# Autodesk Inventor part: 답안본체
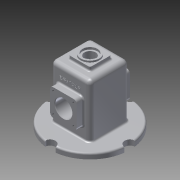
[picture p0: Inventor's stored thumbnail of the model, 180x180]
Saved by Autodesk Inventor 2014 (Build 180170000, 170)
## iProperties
Created: 2018-07
Part Number: 답안본체
Material: Generic
Document SubType Name: Modeling
Designer: kh
Density: 1 g/cm^3
Appearance: Aluminum - Flat
Mass: 336.733 g
Surface Area: 1018.09 cm^2
Volume: 336.733 cm^3
Author: kh
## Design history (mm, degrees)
sketch "Sketch1"
  geometry: C1 r 75 at (0, 0); 1 further point
  constraints: 1 centre point, 1 coincident
  dimensions: "d0" = 150 diameter of C1
extrude "Extrusion1" new body sketch "Sketch1" distance "d1" = 10; taper "d2" = 0 deg
sketch "Sketch2"
  geometry: L1 (0, 0)-(-75, 0); L2 (0, 0)-(0, 75); L3 (0, 0)-(75, 0); L4 (0, 0)-(0, -75); C1 r 10 at (-75, 0); C2 r 10 at (0, 75); C3 r 10 at (75, 0); C4 r 10 at (0, -75); A1 r 75 centre (0, 0) between (-75, 0) and (0, 75) reference; 1 further point
  constraints: 8 end point, 4 centre point, 4 coincident, 4 point on circle, 3 perpendicular, 1 horizontal
  dimensions: "d4" = 20 diameter of C1; "d5" = 20 diameter of C2; "d6" = 20 diameter of C3; "d7" = 20 diameter of C4
extrude "Extrusion2" cut sketch "Sketch2" distance "d8" = 10; taper "d9" = 0 deg
sketch "Sketch3"
  geometry: L1 (37, 37)-(-37, 37); L2 (-37, 37)-(-37, -37); L3 (-37, -37)-(37, -37); L4 (37, -37)-(37, 37); L5 (37, 37)-(-37, -37); L6 (-37, 37)-(37, -37); 1 further point
  constraints: 12 end point, 2 midpoint, 2 parallel, 1 horizontal, 1 perpendicular
  dimensions: "d10" = 74 distance of L1.start L1.end; "d11" = 74 distance of L1.end L2.end
extrude "Extrusion3" join sketch "Sketch3" distance "d12" = 100; taper "d13" = 0 deg
sketch "Sketch4"
  geometry: L1 (62, 70)-(12, 70); L2 (12, 70)-(12, 20); L3 (12, 20)-(62, 20); L4 (62, 20)-(62, 70); L5 (62, 70)-(12, 20); L6 (12, 70)-(62, 20); L7 (46.978, -10)-(27.022, -10) reference; 4 further points
  constraints: 12 end point, 4 midpoint, 2 parallel, 1 horizontal, 1 perpendicular, 1 vertical alignment
  dimensions: "d14" = 50 distance of L1.start L1.end; "d15" = 50 distance of L1.end L2.end; "d16" = 55 distance from line of L7 point (37, 45)
extrude "Extrusion4" join sketch "Sketch4" distance "d17" = 13; taper "d18" = 0 deg
mirror "Mirror1"
sketch "Sketch5"
  geometry: L1 (20, 20)-(-20, 20); L2 (-20, 20)-(-20, -20); L3 (-20, -20)-(20, -20); L4 (20, -20)-(20, 20); L5 (20, 20)-(-20, -20); L6 (-20, 20)-(20, -20); 1 further point
  constraints: 12 end point, 2 midpoint, 2 parallel, 1 horizontal, 1 perpendicular
  dimensions: "d19" = 40 distance of L3.end L2.end; "d20" = 40 distance of L1.end L2.end
extrude "Extrusion5" join sketch "Sketch5" distance "d21" = 7; taper "d22" = 0 deg
sketch "Sketch6"
  geometry: L1 (32, 32)-(-32, 32); L2 (-32, 32)-(-32, -32); L3 (-32, -32)-(32, -32); L4 (32, -32)-(32, 32); L5 (32, 32)-(-32, -32); L6 (-32, 32)-(32, -32); 1 further point
  constraints: 12 end point, 2 midpoint, 2 parallel, 1 horizontal, 1 perpendicular
  dimensions: "d23" = 64 distance of L1.start L1.end; "d24" = 64 distance of L1.end L2.end
extrude "Extrusion6" cut sketch "Sketch6" distance "d25" = 105; taper "d26" = 0 deg
sketch "Sketch7"
  geometry: L1 (-32, 0)-(-32, 105) reference; L2 (-32, 80)-(-25, 77.452); L3 (-32, 55)-(28.433, 55); L4 (32, 0)-(-32, 0) reference; L5 (-25, 77.452)-(-25, 55); 1 further point
  constraints: 6 end point, 3 point on line, 1 perpendicular
  dimensions: "d27" = 55 distance between parallel lines of L4 L3; "d28" = 110 deg angle of L2 L1; "d29" = 7 distance from line of L1 L5.end; "d30" = 50 diameter of L2.start L3
revolve "Revolution1" sketch "Sketch7" stored, may be unused: angle "d31" = 90 deg
mirror "Mirror2"
sketch "Sketch8"
  geometry: C1 r 17.5 at (0, 0); 1 further point
  constraints: 1 centre point, 1 coincident
  dimensions: "d32" = 35 diameter of C1
extrude "Extrusion7" join sketch "Sketch8" distance "d33" = 3; taper "d34" = 0 deg
sketch "Sketch9"
  geometry: C1 r 14 at (0, 0); 1 further point
  constraints: 1 centre point, 1 coincident
  dimensions: "d35" = 28 diameter of C1
extrude "Extrusion8" cut sketch "Sketch9" distance "d36" = 4; taper "d37" = 0 deg
sketch "Sketch10"
  geometry: C1 r 10.5 at (0, 0); 1 further point
  constraints: 1 centre point, 1 coincident
  dimensions: "d38" = 21 diameter of C1
extrude "Extrusion9" cut sketch "Sketch10" stored distance "d39" = 4; taper "d40" = 0 deg
sketch "Sketch11"
  geometry: L1 (62, 70)-(12, 70) reference; L2 (12, 70)-(12, 20) reference; L3 (12, 20)-(62, 20) reference; L4 (62, 20)-(62, 70) reference; L5 (12, 20)-(62, 70); L6 (62, 20)-(12, 70); C1 r 16 at (37, 45); 1 further point
  constraints: 4 end point, 1 centre point, 1 midpoint, 1 perpendicular, 1 point on line
  dimensions: "d41" = 32 diameter of C1
extrude "Extrusion10" cut sketch "Sketch11" stored distance "d42" = 4; taper "d43" = 0 deg
fillet "Fillet1" dims "d44" = 6
sketch "Sketch12"
  geometry: L1 (18, 20)-(56, 20) reference; L2 (62, 26)-(62, 64) reference; L3 (56, 70)-(18, 70) reference; L4 (12, 64)-(12, 26) reference; C1 r 16 at (37, 45) reference; A1 r 6 centre (18, 26) between (12, 26) and (18, 20) reference; A2 r 6 centre (56, 26) between (56, 20) and (62, 26) reference; A3 r 6 centre (56, 64) between (62, 64) and (56, 70) reference; A4 r 6 centre (18, 64) between (18, 70) and (12, 64) reference; 1 further point
  node "Projected Loop3"
hole "Hole1" sketch "Sketch12" diameter "d45" = 3.459; stored, may be unused: countersink angle "d49" = 90 deg, drill point angle "d51" = 118 deg; dims "d46" = 8, "d47" = 4, "d48" = 2, "d50" = 10
mirror "Mirror3"
sketch "Sketch14"
  geometry: L1 (0, 0)-(0, -100) reference; L2 (19.5, -110)-(54.5, -110) reference; 2 further points
  constraints: 1 other
  dimensions: "d52" = 37 distance from line of point (37, -80) L1; "d53" = 30 distance from line of point (37, -80) L2
emboss "Emboss1" sketch "Sketch14" dims "d10" = 74, "d11" = 74, "d54" = 0.5, "d55" = 0
fillet "Fillet2" dims "d56" = 8
chamfer "Chamfer1" distance "d57" = 1; stored, may be unused: second distance "d58" = 2, angle "d59" = 45 deg
fillet "Fillet3" dims "d60" = 3
fillet "Fillet4" dims "d61" = 3
body "Solid1"
node "Projected Loop1"
node "Projected Loop2"
